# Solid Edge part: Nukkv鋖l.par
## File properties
Author: Türk
Template: Iso Part.par
Last saved by: Türk
Revision: 30
Application: Solid Edge
Accuracy: 0,990
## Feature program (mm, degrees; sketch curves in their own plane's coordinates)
pattern "PatternOccurrence_2"  XOffset = 45 deg
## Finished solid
Body 1: solid body, 158 faces, 346 edges, 200 vertices.
  Faces by surface: cylinder 79, plane 79
  Edges by curve: line 188, circle 158
Body 2: sheet body, 1 face, 138 edges, 138 vertices.
  Faces by surface: plane 1
  Edges by curve: line 136, circle 2
Bounding box of the edges (mm): 686.000 x 43.185 x 41.637, from (-4, -21.5925, -19.6372) to (682, 21.5925, 22).
Cylindrical faces by radius (mm): R1.75 x8, R5 x20, R9 x8, R10 x17, R12 x16, R22 x10
Planar faces by outward normal: +x 17, +y 3, +z 3, -x 18, -y 3, -z 3, oblique 32
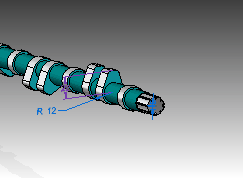
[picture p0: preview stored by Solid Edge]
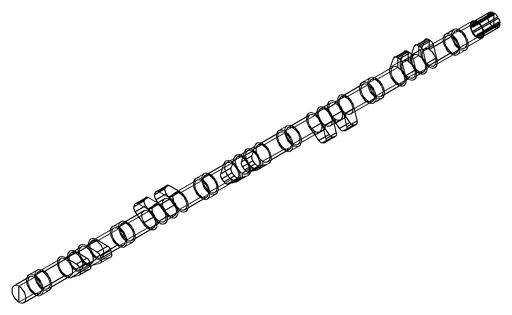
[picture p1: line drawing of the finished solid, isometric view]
